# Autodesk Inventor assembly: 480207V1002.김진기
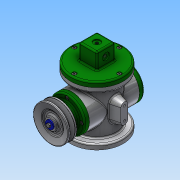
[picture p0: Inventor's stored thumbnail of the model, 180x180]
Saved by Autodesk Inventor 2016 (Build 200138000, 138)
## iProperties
Created: 2018-02
Part Number: 480207V1002.김진기
Material: 일반
Document SubType Name: Assembly
Designer: Administrator
Author: Administrator
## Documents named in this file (18)
- C:\Users\Administrator\Desktop\480207V1002.김진기\480207V1002.김진기.iam
- C:\Users\Administrator\Desktop\480207V1002.김진기\480207V1002.김진기.ipt
- C:\Users\Administrator\Desktop\480207V1002.김진기\뒤커버.ipt
- C:\Users\Administrator\Desktop\480207V1002.김진기\베어링 17 x 40 x 12.ipt
- C:\Users\Administrator\Desktop\480207V1002.김진기\앞커버.ipt
- C:\Users\Administrator\Desktop\480207V1002.김진기\오일 실 17 30 8.ipt
- C:\Users\Administrator\Desktop\480207V1002.김진기\덮개.ipt
- C:\Users\Administrator\Desktop\480207V1002.김진기\편심축.ipt
- C:\Users\Administrator\Desktop\480207V1002.김진기\V-벨트풀리.ipt
- C:\Users\Administrator\Desktop\480207V1002.김진기\키 4 x 4 x 12.ipt
- C:\Users\Administrator\Desktop\480207V1002.김진기\볼트 M4 x 10.ipt
- C:\Users\Administrator\Desktop\480207V1002.김진기\와셔 4x16.ipt
- C:\Users\Administrator\Desktop\480207V1002.김진기\링크.ipt
- C:\Users\Administrator\Desktop\480207V1002.김진기\슬라이더.ipt
- C:\Users\Administrator\Desktop\480207V1002.김진기\클레비스 핀 6 x 22.ipt
- 클레비스 핀 6 x 22.ipt
- C:\Users\Administrator\Desktop\480207V1002.김진기\볼트 M4 x 8.ipt
- C:\Users\Administrator\Desktop\480207V1002.김진기\E-링.ipt
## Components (3 placed, 3 different names)
1. 480207V1002.김진기:1 — 각도:2, 각도:4
2. V-벨트풀리:1 — 각도:3
3. E-링:1
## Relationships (3: Angle 3)
- 각도:2 [Angle]: 480207V1002.김진기:1
- 각도:3 [Angle]: V-벨트풀리:1
- 각도:4 [Angle]: 480207V1002.김진기:1
